Omron CX-Programmer project NewProject (CX-Programmer 9.03)

# PLC NewPLC1: CP1L M

## Program NewProgram1 (cyclic task 0)
; This purpose of this program is to show how to use the GRY instruction in the CP1L to convert the encoder's gray codes into degrees. / This example uses a CP1L PLC and an E6F-AG5B-720 Encoder. / The encoder is being wired to CIO 2 of the CP1L. / The E6F-AG5B-720 is a 10 bit Gray code encoder with 720 pulses per revolution. / The gray codes range from 152 to 871 and NOT 0 to 719. The 152 is used in D42 in hex. / For more information on the GRY instruction please reference W451 - CP1H/CP1L Progarmming Manual. / For more information on the E6F encoder please reference F824 E6F-A Rotary Encoder Data sheet.
Local symbols
CIO_2 2 CHANNEL
Control_Word_C D40 CHANNEL
Control_Word_Cplus1 D41 CHANNEL
Control_Word_Cplus2 D42 CHANNEL
Converted_Angle D4294 DWORD

### Section Section1

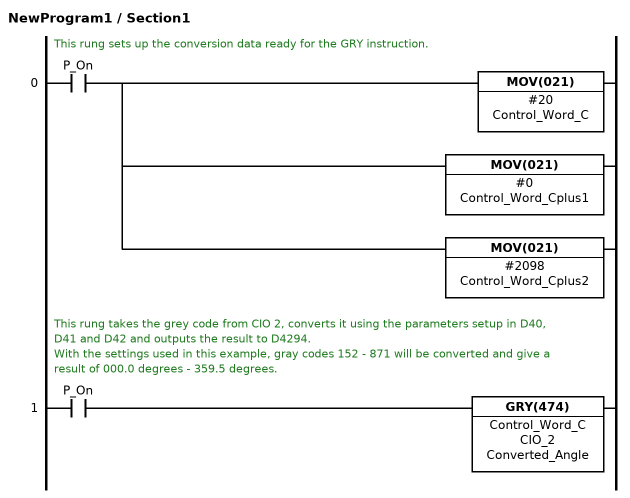
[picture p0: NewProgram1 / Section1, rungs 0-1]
; rung 0: This rung sets up the conversion data ready for the GRY instruction.
LD P_On
MOV(021) #20 Control_Word_C  // Set D40 to #0020. / 0 = Operating Mode = Gray Binary Code Conversion. / 0 = Do not use. / 2 = Conversion Mode = 360 degrees Mode / 0 = Resolution = Set in D42
MOV(021) #0 Control_Word_Cplus1  // Set D41 to #0000 / Zero Point Compensation.
MOV(021) #2098 Control_Word_Cplus2  // Set D42 to #2098 / 2 = User Specified Resolution = 720 ppr / 098 = Encoder Remainder Compensation = 098 hex or 152 dec
; rung 1: This rung takes the grey code from CIO 2, converts it using the parameters setup in D40, D41 and D42 and outputs the result to D4294. / With the settings used in this example, gray codes 152 - 871 will be converted and give a result of 000.0 degrees - 359.5 degrees.
LD P_On
GRY(474) Control_Word_C CIO_2 Converted_Angle
; rung 2: Tested Conversion Values: / Gray Code 152 = #00D4 = 000.0 degrees / Gray Code 512 = #0300 = 180.0 degrees / Gray Code 692 = #03EE = 270.0 degrees / Gray Code 782 = #0289 = 315.0 degrees / Gray Code 871 = #02D4 = 359.5 degrees / Put the # values into CIO 2 to test without an encoder.

### Section END
; rung 0
END(001)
